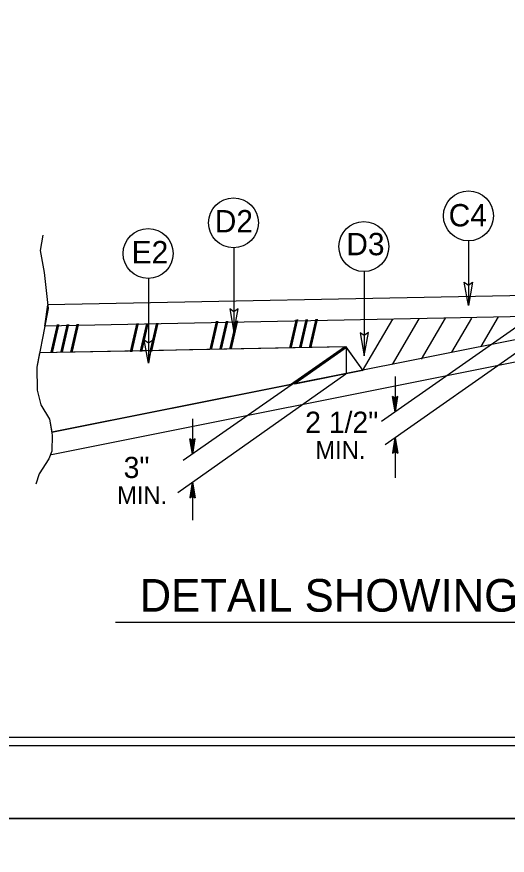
# Model space of a CAD drawing. Extents: x 1901718 to 1902220, y 193828 to 194187.
# Drawn here: x 1901988.77 to 1902003.79, y 194046.89 to 194072.58 of the extents above; entities that cross this region are included whole.
import ezdxf

# ---------------------------------------------------------------- set-up
doc = ezdxf.new("R2010")
doc.units = 0
for name, color, linetype in [('Old_Level_1', 7, 'Continuous'), ('Old_Level_11', 7, 'Continuous'), ('Old_Level_20', 7, 'Continuous'), ('Old_Level_21', 7, 'Continuous'), ('Sheet Border Standard 30in CELL', 7, 'Continuous'), ('Sheet Cutting Line CELL', 7, 'Continuous'), ('Sheet Plot Border Inside CELL', 7, 'Continuous'), ('Sheet Plot Border Outside CELL', 7, 'Continuous')]:
    doc.layers.add(name, color=color, linetype=linetype)

msp = doc.modelspace()

# ---------------------------------------------------------------- linework, layer by layer
at = {"layer": 'Old_Level_1'}
for p, q in [((1902004.51, 194063.386), (1901999.935, 194060.183)), ((1902003.505, 194063.386), (1902002.976, 194062.478)), ((1902000.27, 194063.313), (1901999.347, 194061.732)), ((1902001.08, 194063.33), (1902000.264, 194061.928)), ((1902001.882, 194063.346), (1902001.149, 194062.089)), ((1902002.691, 194063.344), (1902002.083, 194062.303)), ((1902004.521, 194062.604), (1902000.044, 194059.469)), ((1901998.85, 194062.471), (1901989.466, 194062.283)), ((1902005.947, 194062.385), (1901989.833, 194059.162)), ((1901998.85, 194062.471), (1901993.868, 194058.982)), ((1901999.36, 194061.754), (1901998.85, 194062.471)), ((1901998.85, 194062.471), (1901998.85, 194061.652)), ((1901998.846, 194061.627), (1901993.695, 194058.001)), ((1901998.85, 194061.653), (1901997.216, 194061.326)), ((1901997.216, 194061.326), (1901989.839, 194059.851)), ((1902000.352, 194061.563), (1902000.352, 194060.475)), ((1902000.352, 194060.475), (1902000.268, 194060.952)), ((1902000.352, 194060.89), (1902000.268, 194060.952)), ((1902000.352, 194060.475), (1902000.28, 194060.943)), ((1902000.292, 194060.934), (1902000.352, 194060.475)), ((1902000.352, 194060.475), (1902000.304, 194060.926)), ((1902000.316, 194060.917), (1902000.352, 194060.475)), ((1902000.352, 194060.475), (1902000.328, 194060.908)), ((1902000.34, 194060.899), (1902000.352, 194060.475)), ((1902000.352, 194060.475), (1902000.437, 194060.952)), ((1902000.437, 194060.952), (1902000.352, 194060.89)), ((1902000.425, 194060.943), (1902000.352, 194060.475)), ((1902000.352, 194060.475), (1902000.412, 194060.934)), ((1902000.4, 194060.926), (1902000.352, 194060.475)), ((1902000.352, 194060.475), (1902000.388, 194060.917)), ((1902000.376, 194060.908), (1902000.352, 194060.475)), ((1902000.352, 194060.475), (1902000.364, 194060.899)), ((1902000.352, 194060.89), (1902000.352, 194060.475)), ((1901994.148, 194060.262), (1901994.148, 194059.177)), ((1901994.148, 194059.177), (1901994.063, 194059.655)), ((1901994.148, 194059.593), (1901994.063, 194059.655)), ((1901994.148, 194059.177), (1901994.075, 194059.647)), ((1901994.088, 194059.637), (1901994.148, 194059.177)), ((1901994.148, 194059.177), (1901994.101, 194059.629)), ((1901994.112, 194059.62), (1901994.148, 194059.177)), ((1901994.148, 194059.177), (1901994.124, 194059.611)), ((1901994.136, 194059.602), (1901994.148, 194059.177)), ((1901994.148, 194059.177), (1901994.232, 194059.655)), ((1901994.232, 194059.655), (1901994.148, 194059.593)), ((1901994.22, 194059.647), (1901994.148, 194059.177)), ((1901994.148, 194059.177), (1901994.208, 194059.637)), ((1901994.196, 194059.629), (1901994.148, 194059.177)), ((1901994.148, 194059.177), (1901994.184, 194059.62)), ((1901994.173, 194059.611), (1901994.148, 194059.177)), ((1901994.148, 194059.177), (1901994.16, 194059.602)), ((1901994.148, 194059.593), (1901994.148, 194059.177)), ((1902000.352, 194059.685), (1902000.268, 194059.207)), ((1902000.28, 194059.217), (1902000.352, 194059.685)), ((1902000.352, 194059.685), (1902000.292, 194059.225)), ((1902000.304, 194059.235), (1902000.352, 194059.685)), ((1902000.352, 194059.685), (1902000.316, 194059.243)), ((1902000.328, 194059.252), (1902000.352, 194059.685)), ((1902000.352, 194059.685), (1902000.34, 194059.261)), ((1902000.352, 194059.685), (1902000.352, 194058.459)), ((1902000.352, 194059.685), (1902000.437, 194059.207)), ((1902000.352, 194059.269), (1902000.352, 194059.685)), ((1902000.364, 194059.261), (1902000.352, 194059.685)), ((1902000.352, 194059.685), (1902000.376, 194059.252)), ((1902000.388, 194059.243), (1902000.352, 194059.685)), ((1902000.352, 194059.685), (1902000.4, 194059.235)), ((1902000.412, 194059.225), (1902000.352, 194059.685)), ((1902000.352, 194059.685), (1902000.425, 194059.217)), ((1902000.268, 194059.207), (1902000.352, 194059.269)), ((1902000.352, 194059.269), (1902000.437, 194059.207)), ((1901994.148, 194058.319), (1901994.063, 194057.842)), ((1901994.076, 194057.851), (1901994.148, 194058.319)), ((1901994.148, 194058.319), (1901994.088, 194057.86)), ((1901994.101, 194057.868), (1901994.148, 194058.319)), ((1901994.148, 194058.319), (1901994.112, 194057.877)), ((1901994.124, 194057.886), (1901994.148, 194058.319)), ((1901994.148, 194058.319), (1901994.136, 194057.894)), ((1901994.148, 194058.319), (1901994.148, 194057.159)), ((1901994.148, 194058.319), (1901994.232, 194057.842)), ((1901994.148, 194057.904), (1901994.148, 194058.319)), ((1901994.16, 194057.894), (1901994.148, 194058.319)), ((1901994.148, 194058.319), (1901994.173, 194057.886)), ((1901994.185, 194057.877), (1901994.148, 194058.319)), ((1901994.148, 194058.319), (1901994.196, 194057.868)), ((1901994.208, 194057.86), (1901994.148, 194058.319)), ((1901994.148, 194058.319), (1901994.22, 194057.851)), ((1901994.063, 194057.842), (1901994.148, 194057.904)), ((1901994.148, 194057.904), (1901994.232, 194057.842))]:
    msp.add_line(p, q, dxfattribs=at)
msp.add_lwpolyline([(1901989.566, 194065.896), (1901989.479, 194065.42), (1901989.61, 194064.744), (1901989.724, 194063.649), (1901989.566, 194062.785), (1901989.379, 194061.849), (1901989.393, 194061.143), (1901989.509, 194060.697), (1901989.768, 194060.25), (1901989.854, 194059.761), (1901989.84, 194059.271), (1901989.753, 194059.04), (1901989.451, 194058.579), (1901989.351, 194058.262)], dxfattribs=at)
at = {"layer": 'Old_Level_11'}
for p, q in [((1902002.596, 194065.717), (1902002.596, 194063.739)), ((1901995.418, 194065.504), (1901995.418, 194062.923)), ((1901999.409, 194064.775), (1901999.409, 194062.194)), ((1901992.797, 194064.563), (1901992.797, 194061.968)), ((1902005.952, 194064.077), (1901989.717, 194063.753)), ((1901989.624, 194063.101), (1901989.717, 194063.753)), ((1902004.528, 194063.399), (1901989.624, 194063.101)), ((1902005.977, 194063.079), (1901989.839, 194059.851)), ((1901992.73, 194062.348), (1901989.466, 194062.283)), ((1901998.805, 194062.47), (1901994.053, 194062.375)), ((1901997.151, 194061.312), (1901998.805, 194062.47)), ((1901989.466, 194062.283), (1901989.379, 194061.849)), ((1901989.838, 194059.851), (1901997.151, 194061.312)), ((1901991.79, 194054.031), (1902021.085, 194054.031))]:
    msp.add_line(p, q, dxfattribs=at)
for points in [[(1902002.719, 194064.447), (1902002.596, 194063.739), (1902002.47, 194064.451), (1902002.596, 194064.361)], [(1901995.296, 194063.632), (1901995.418, 194062.923), (1901995.544, 194063.636), (1901995.418, 194063.545)], [(1901999.287, 194062.902), (1901999.409, 194062.194), (1901999.535, 194062.906), (1901999.409, 194062.816)], [(1901992.919, 194062.676), (1901992.797, 194061.968), (1901992.671, 194062.68), (1901992.797, 194062.59)], [(1901999.36, 194061.754), (1901998.865, 194062.45), (1901997.278, 194061.339)]]:
    msp.add_lwpolyline(points, close=True, dxfattribs=at)
for points in [[(1901994.053, 194062.375), (1901992.863, 194062.351), (1901992.797, 194061.968), (1901992.73, 194062.348)], [(1901989.379, 194061.849), (1901989.393, 194061.143), (1901989.509, 194060.697)], [(1901989.509, 194060.697), (1901989.768, 194060.25), (1901989.838, 194059.851)]]:
    msp.add_lwpolyline(points, dxfattribs=at)
for centre in [(1902002.597, 194066.482), (1901995.404, 194066.27), (1901999.395, 194065.54), (1901992.79, 194065.329)]:
    msp.add_circle(centre, 0.765, dxfattribs=at)
at = {"layer": 'Sheet Border Standard 30in CELL'}
msp.add_lwpolyline([(1902132.544, 194155.514), (1901982.544, 194155.514), (1901982.544, 194050.514), (1902132.544, 194050.514)], close=True, dxfattribs=at)
at = {"layer": 'Sheet Cutting Line CELL'}
for p, q in [((1901965.844, 194048.014), (1902134.244, 194048.014)), ((1902134.244, 194048.014), (1901965.844, 194048.014))]:
    msp.add_line(p, q, dxfattribs=at)
at = {"layer": 'Sheet Plot Border Inside CELL'}
msp.add_lwpolyline([(1902133.794, 194155.769), (1901967.144, 194155.769), (1901967.144, 194050.259), (1902133.794, 194050.259)], close=True, dxfattribs=at)
at = {"layer": 'Sheet Plot Border Outside CELL'}
for points in [[(1902134.244, 194158.014), (1901965.844, 194158.014), (1901965.844, 194048.014), (1902134.244, 194048.014)], [(1902134.244, 194048.014), (1901965.844, 194048.014), (1901965.844, 193938.014), (1902134.244, 193938.014)]]:
    msp.add_lwpolyline(points, close=True, dxfattribs=at)

# ---------------------------------------------------------------- texts
at = {"layer": 'Old_Level_1'}
for height, rotation, p in [(0.8142, 1.1447, (1901989.789, 194062.294)), (0.8142, 1.1464, (1901992.223, 194062.323)), (0.8139, 1.1445, (1901994.662, 194062.395)), (0.8139, 1.1463, (1901997.103, 194062.445))]:
    msp.add_text('/// ', height=height, rotation=rotation, dxfattribs=at).set_placement(p)
at = {"layer": 'Old_Level_20'}
for s, height, p in [('C4', 0.6851, (1902001.993, 194066.159)), ('D2', 0.6851, (1901994.83, 194065.976)), ('D3', 0.6851, (1901998.858, 194065.276)), ('E2', 0.6851, (1901992.286, 194065.027)), ('2 1/2"', 0.6491, (1901997.599, 194059.834)), ('3"', 0.6491, (1901992.04, 194058.45))]:
    msp.add_text(s, height=height, dxfattribs=at).set_placement(p)
at = {"layer": 'Old_Level_21'}
for s, height, p in [('MIN.', 0.5424, (1901997.911, 194059.037)), ('MIN.', 0.5424, (1901991.841, 194057.652)), ('DETAIL SHOWING METHOD OF WEDGING', 1, (1901992.529, 194054.355))]:
    msp.add_text(s, height=height, dxfattribs=at).set_placement(p)

doc.saveas('drawing.dxf')
